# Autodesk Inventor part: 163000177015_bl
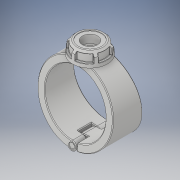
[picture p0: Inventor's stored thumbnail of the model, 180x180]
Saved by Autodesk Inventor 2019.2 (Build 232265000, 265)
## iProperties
Created: 2022-02
Part Number: 163000177015_bl
Material: Generic
Description: Plassadle Threaded 177x1 1/2''
Document SubType Name: Modeling
Designer: comp2
Density: 1 g/cm^3
Appearance: Default
Author: comp2
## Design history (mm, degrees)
derived "16300.ipt"
feature "Solid1::16300.ipt" dims "ScaleForDerivedMember" = 10
feature "Solid2::16300.ipt" dims "ScaleForDerivedMember" = 10
feature "Solid3::16300.ipt" dims "ScaleForDerivedMember" = 10
feature "Solid4::16300.ipt" dims "ScaleForDerivedMember" = 10
tag "TaggingFeature1"
body "Solid1"
body "Solid2"
body "Solid3"
body "Solid4"
other parameters: "d0" = 177 [user parameter], "d3" = 88.5 [user parameter], "d7" = 209 [user parameter], "d8" = 85 deg [user parameter], "d9" = 45 deg [user parameter], "d10" = 102 [user parameter], "d11" = 49 [user parameter], "d12" = 25.27 [user parameter], "d13" = 42.84 [user parameter], "d14" = 67.2675 [user parameter], "d42" = 4.3 [user parameter], "d49" = 4.4 [user parameter], "d51" = 0 [user parameter], "d52" = 30.1 [user parameter], "d53" = 121 [user parameter], "d54" = 38.5 [user parameter], "d55" = 0 [user parameter], "d56" = 22 [user parameter], "d57" = 22 [user parameter], "d59" = 0 [user parameter], "d61" = 0 [user parameter], "d62" = 38.5 [user parameter], "d63" = 0 [user parameter], "d65" = 0 [user parameter], "d67" = 0 [user parameter], "d69" = 0 [user parameter], "d70" = 1 [user parameter], "d71" = 105.6 [user parameter], "d72" = 0 [user parameter], "d73" = 2 [user parameter], "d78" = 86.7 [user parameter], "d79" = 5.1 [user parameter], "d80" = 60 deg [user parameter], "d81" = 5.1 [user parameter], "d84" = 0 [user parameter], "d85" = 1 [user parameter], "d87" = 360 deg [user parameter], "d122" = 52 [user parameter], "d124" = 42.80128 [user parameter], "d125" = 1.805 [user parameter], "d127" = 255 [user parameter], "d129" = 44.845 [user parameter], "d130" = 38.11825 [user parameter], "d131" = 33.8 [user parameter], "d132" = 45 deg [user parameter], "d133" = 23.66 [user parameter], "d134" = 22.4225 [user parameter], "d136" = 0 [user parameter], "d138" = 0 [user parameter], "d" = 177 [user parameter], "d1" = 25 [user parameter], "E_" = 54 [user parameter], "E1" = 102 [user parameter], "H1" = 255 [user parameter], "H2" = 52 [user parameter], "H3" = 78 [user parameter], "H_costum" = 49 [user parameter], "Rp" = 44.845 [user parameter], "d128" = 36.1 [user parameter]
